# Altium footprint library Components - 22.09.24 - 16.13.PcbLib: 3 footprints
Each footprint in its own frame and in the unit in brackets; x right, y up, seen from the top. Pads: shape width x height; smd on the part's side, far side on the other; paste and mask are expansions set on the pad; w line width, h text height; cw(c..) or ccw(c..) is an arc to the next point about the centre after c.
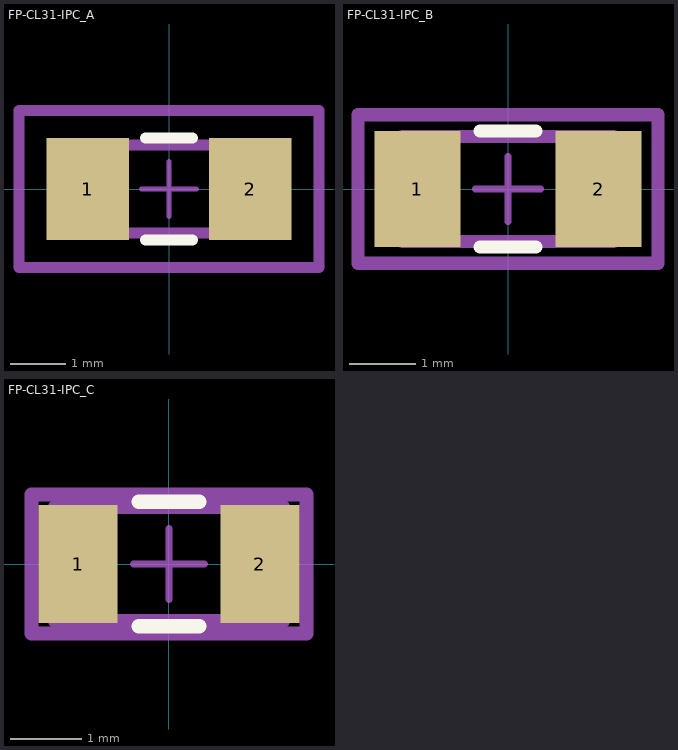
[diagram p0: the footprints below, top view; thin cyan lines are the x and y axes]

## FP-CL31-IPC_A [mm]
pads (2):
  rect 1.505x1.858 smd paste+0 mask+0: 1(-1.476,0) 2(1.476,0)
Top Overlay:
  lines w0.2: -0.424,-0.929 0.424,-0.929 ; -0.424,0.929 0.424,0.929
Top Assembly:
  lines w0.2: -2.729,-1.429 2.729,-1.429 2.729,1.429 -2.729,1.429 -2.729,-1.429
  text ".Designator" at 0,0.188 h1
Top 3D Body:
  lines w0.2: -1.6,-0.8 1.6,-0.8 1.6,0.8 -1.6,0.8 -1.6,-0.8
Top Courtyard:
  lines w0.2: -2.729,-1.429 2.729,-1.429 2.729,1.429 -2.729,1.429 -2.729,-1.429
Top Component Center:
  lines w0.1: -0.5,0 0.5,0 ; 0,-0.5 0,0.5
3D body "Cap_Samsung_CL31B105KOFNNNE_eec.STEP": height 0.25, standoff 0, extent -2.729,-1.429 2.729,1.429

## FP-CL31-IPC_B [mm]
pads (2):
  rect 1.305x1.758 smd paste+0 mask+0: 1(-1.376,0) 2(1.376,0)
Top Overlay:
  lines w0.2: -0.424,-0.879 0.424,-0.879 ; -0.424,0.879 0.424,0.879
Top Assembly:
  lines w0.2: -2.279,-1.129 2.279,-1.129 2.279,1.129 -2.279,1.129 -2.279,-1.129
  text ".Designator" at 0,0.188 h1
Top 3D Body:
  lines w0.2: -1.6,-0.8 1.6,-0.8 1.6,0.8 -1.6,0.8 -1.6,-0.8
Top Courtyard:
  lines w0.2: -2.279,-1.129 2.279,-1.129 2.279,1.129 -2.279,1.129 -2.279,-1.129
Top Component Center:
  lines w0.1: -0.5,0 0.5,0 ; 0,-0.5 0,0.5
3D body "Cap_Samsung_CL31B105KOFNNNE_eec.STEP": height 0.25, standoff 0, extent -2.279,-1.129 2.279,1.129

## FP-CL31-IPC_C [mm]
pads (2):
  rect 1.105x1.658 smd paste+0 mask+0: 1(-1.276,0) 2(1.276,0)
Top Overlay:
  lines w0.2: -0.424,-0.875 0.424,-0.875 ; -0.424,0.875 0.424,0.875
Top Assembly:
  lines w0.2: -1.929,-0.975 1.929,-0.975 1.929,0.975 -1.929,0.975 -1.929,-0.975
  text ".Designator" at 0,0.188 h1
Top 3D Body:
  lines w0.2: -1.6,-0.8 1.6,-0.8 1.6,0.8 -1.6,0.8 -1.6,-0.8
Top Courtyard:
  lines w0.2: -1.929,-0.975 1.929,-0.975 1.929,0.975 -1.929,0.975 -1.929,-0.975
Top Component Center:
  lines w0.1: -0.5,0 0.5,0 ; 0,-0.5 0,0.5
3D body "Cap_Samsung_CL31B105KOFNNNE_eec.STEP": height 0.25, standoff 0, extent -1.929,-0.975 1.929,0.975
